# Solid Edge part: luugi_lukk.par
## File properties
Author: Mac
Template: Normal.par
Last saved by: Mac
Revision: 1
Application: Solid Edge
Density: 7750,000 kg/m^3
Accuracy: 0,990
Material: Stainless steel
Face Style: Steel
Fill Style: ANSI32(Steel)
Virtual Style: Stainless steel
Coef. of Thermal Exp: 1.6e-05
Thermal Conductivity: 17.0
Specific Heat: 502.0
Modulus of Elasticity: 193053196000.0
Poission's Ratio: 0.29
Yield Stress: 310264065.0
Ultimate Stress: 641212401.0
Elongation: 0.0
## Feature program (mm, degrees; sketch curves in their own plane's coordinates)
sketch for "unnamed RevolvedProtrusion 1" plane through (0, 0, 0) normal (0, -1, 0) x-axis (1, 0, 0)
  line (0.7, 0.8646) -> (0.76, 0.8646)
  line (0.76, 0.9246) -> (0.76, 0.8646)
  line (0, 0.9246) -> (0.76, 0.9246)
  line (0, 0.9246) -> (0, 0.7446)
  line (0, 0.7446) -> (0.7, 0.7446)
  line (0.7, 0.8646) -> (0.7, 0.7446)
revolve "unnamed RevolvedProtrusion 1" add full turn 360 deg
sketch for "unnamed Cutout 1" plane through (0, 0, 0.9246) normal (0, 0, 1) x-axis (1, 0, 0)
  circle centre (0, 0) radius 0.68
extrude "unnamed Cutout 1" cut finite 0.16 along -normal
fillet "Round_2" radius 0.04
sketch for "ExtrudedProtrusion_1" plane through (0, 0, 0) normal (0, -1, 0) x-axis (1, 0, 0)
  line (-0.6, 0.7646) -> (-0.6, 0.8246)
  arc centre (-0.56, 0.8246) radius 0.04 from (-0.6, 0.8246) to (-0.52, 0.8246) cw
  line (-0.52, 0.7646) -> (-0.52, 0.8246)
  line (-0.6, 0.7646) -> (-0.52, 0.7646)
extrude "ExtrudedProtrusion_1" add finite 0.05 symmetric
sketch for "unnamed Protrusion 1" plane through (0.04, 0, 0.8196) normal (-0.008333, 0, -0.999965) x-axis (0.999965, 0, -0.008333)
  arc centre (0.2023, 0.195) radius 0.1 from (0.2023, 0.095) to (0.2931, 0.2369) ccw
  line (0.2023, 0.095) -> (-0.64, 0.095)
  line (-0.64, 0.095) -> (-0.64, 0.035)
  line (-0.5495, 0.035) -> (-0.64, 0.035)
  line (-0.5495, -0.035) -> (-0.5495, 0.035)
  line (-0.64, -0.035) -> (-0.5495, -0.035)
  line (-0.64, -0.035) -> (-0.64, -0.095)
  line (0.2023, -0.095) -> (-0.64, -0.095)
  arc centre (0.2023, -0.195) radius 0.1 from (0.2931, -0.2369) to (0.2023, -0.095) ccw
  arc centre (-0.2205, 0) radius 0.5656 from (0.2931, -0.2369) to (-0.0631, -0.5433) cw
  arc centre (-0.0494, -0.5906) radius 0.0493 from (-0.0631, -0.5433) to (-0.0502, -0.6399) ccw
  arc centre (-0.0494, 0.5906) radius 0.0493 from (-0.0631, 0.5433) to (-0.0502, 0.6399) cw
extrude "unnamed Protrusion 1" add to key point symmetric
fillet "Round_3" radius 0.03
fillet "Round_4" radius 0.03
sketch for "ExtrudedProtrusion_5" plane through (0, 0, 0.0446) normal (0, 0, -1) x-axis (1, 0, 0)
  line (-0.56, 0.1624) -> (-1.35, 0.1624)
  arc centre (-1.35, 0.1124) radius 0.05 from (-1.35, 0.1624) to (-1.4, 0.1124) ccw
  line (-1.4, 0.1124) -> (-1.4, -0.1124)
  arc centre (-1.35, -0.1124) radius 0.05 from (-1.35, -0.1624) to (-1.4, -0.1124) cw
  line (-0.56, -0.1624) -> (-1.35, -0.1624)
extrude "ExtrudedProtrusion_5" add finite 0.12 along +normal  Profile_Plane1_Distance = 0.7 mm
sketch for "unnamed Cutout 2" #1 plane through (-0.955, -0.1624, -0.0154) normal (0, -1, 0) x-axis (1, 0, 0)
  line (0.2748, 0.02) -> (0.1684, -0.06)
  line (-0.5147, -0.06) -> (0.1684, -0.06)
  line (-0.5147, -0.1284) -> (-0.5147, -0.06)
  line (0.575, -0.1284) -> (-0.5147, -0.1284)
  line (0.575, 0.02) -> (0.575, -0.1284)
  line (0.2748, 0.02) -> (0.575, 0.02)
sketch for "unnamed Cutout 2" #2 plane through (-0.955, -0.1624, -0.0154) normal (0, -1, 0) x-axis (1, 0, 0)
  line (-0.5147, -0.02) -> (0.155, -0.02)
  line (0.155, -0.02) -> (0.2615, 0.06)
  line (0.2615, 0.1132) -> (0.2615, 0.06)
  line (-0.5147, 0.1132) -> (0.2615, 0.1132)
  line (-0.5147, -0.02) -> (-0.5147, 0.1132)
extrude "unnamed Cutout 2" cut through along -normal
sketch for "unnamed Protrusion 2" plane through (0, 0, 0.7446) normal (0, 0, -1) x-axis (1, 0, 0)
  circle centre (-0.56, 0) radius 0.1
extrude "unnamed Protrusion 2" add to key point along +normal
sketch for "ExtrudedProtrusion_4" #1 plane through (0, 0, 0.7446) normal (0, 0, -1) x-axis (1, 0, 0)
sketch for "ExtrudedProtrusion_4" #2 plane through (0, 0, 0.7446) normal (0, 0, -1) x-axis (1, 0, 0)
  circle centre (-0.6667, 0.0226) radius 0.0051
sketch for "ExtrudedProtrusion_4" #3 plane through (0, 0, 0.7446) normal (0, 0, -1) x-axis (1, 0, 0)
  circle centre (-0.6667, -0.0237) radius 0.0053
extrude "ExtrudedProtrusion_4" add finite 0.01 along +normal
fillet "Round_5" radius 0.05
fillet "Round_6" radius 0.05
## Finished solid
Body 1: sheet body, 1 face, 4 edges, 4 vertices.
  Faces by surface: plane 1
  Edges by curve: line 4
Body 2: solid body, 86 faces, 188 edges, 108 vertices, 2 separate solids.
  Faces by surface: cylinder 35, plane 28, torus 15, sphere 4, blend 3, swept 1
  Edges by curve: circle 99, line 83, intersection 6
Bounding box of the edges (mm; curved faces can reach further): 2.160 x 1.520 x 0.960, from (-1.4, -0.76, -0.0754) to (0.76, 0.76, 0.8846).
Cylindrical faces by radius (mm): R0.0051 x1, R0.0053 x1, R0.011 x1, R0.0112 x1, R0.0198 x1, R0.02 x1, R0.03 x10, R0.04 x1, R0.0493 x2, R0.05 x6, R0.1 x3, R0.1153 x1, R0.1624 x1, R0.5656 x2, R0.68 x1, R0.7 x1, R0.76 x1
Toroidal faces (ring radius, tube radius in mm): R0.0193 r0.03 x4, R0.13 r0.03 x4, R0.15 r0.05 x1, R0.5956 r0.03 x4, R0.64 r0.04 x1, R0.72 r0.04 x1
Spherical faces by radius (mm): R0.03 x4
Planar faces by outward normal: +x 1, +y 4, +z 3, -x 2, -y 4, -z 7, oblique 7
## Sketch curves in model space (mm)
line (-0.56, 0, 0.8246) -> (0.64, 0, 0.8146)
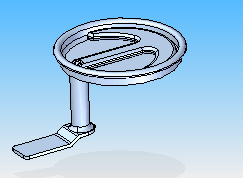
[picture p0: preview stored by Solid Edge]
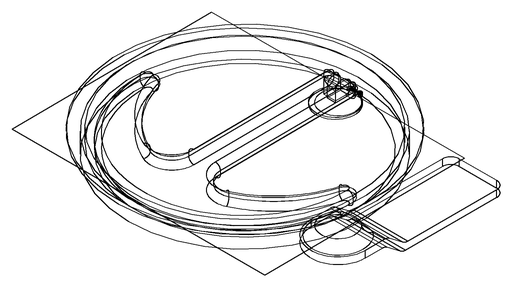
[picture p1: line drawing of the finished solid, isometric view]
